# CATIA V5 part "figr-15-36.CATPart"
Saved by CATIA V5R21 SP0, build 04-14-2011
Part number: Part1
Bounding box of the stored display mesh (mm): x -63.331 to 107.433, y -39.139 to 39.139, z 0 to 70.926
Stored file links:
  D:\CATIA V5R21 E-RESOURCES\CATIA-V5R21\catia-v5r21-prt\c15-catia-v5r20-prt\c15-catia-v5r21-figr-15-36.CATPart
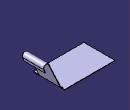
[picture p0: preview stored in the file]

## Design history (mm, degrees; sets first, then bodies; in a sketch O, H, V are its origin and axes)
SheetMetalParameters1: Thickness 1, BendRadius 2, KFactor 0.400515 {= log(min(100,max(20*SheetMetalParameters1.BendRadius,SheetMetalParameters1.Thickness)/SheetMetalParameters1.Thickness))/log(100)/2}, ReliefRadialLength 1, ReliefAxialLength 2, MinimumBendRadius 0
Body1 (main body)
  Sketch1 on xy-plane, origin (0, 0, 0), H (1, 0, 0), V (0, 1, 0)
    line L1 (-63.3311, 39.1393) -> (63.3311, 39.1393)
    line L2 (63.3311, 39.1393) -> (63.3311, -39.1393)
    line L3 (63.3311, -39.1393) -> (-63.3311, -39.1393)
    line L4 (-63.3311, -39.1393) -> (-63.3311, 39.1393)
    horizontal: L1 H, L3 H
    vertical: L2 V, L4 V
    symmetry: L4 L2 V, L1 L3 H
  Wall1: Thickness 1, Profile Sketch1
  d_NewWallOnEdge1: NewWallOnEdge_Edge edge [face of Wall1 | face of Wall1], NewWallOnEdge_Length 67, NewWallOnEdge_HeightLimitOffset 0, NewWallOnEdge_WidthOffset1 -16, NewWallOnEdge_WidthOffset2 -9, NewWallOnEdge_Angle 115, NewWallOnEdge_BendRadiusValue 2 {= SheetMetalParameters1.BendRadius}, NewWallOnEdge_BendTable SheetMetalParameters1, KFacteur 0.400515 {= log(min(100,max(20*d_NewWallOnEdge1.Radius,SheetMetalParameters1.Thickness)/SheetMetalParameters1.Thickness))/log(100)/2}
  Flange1: Angle 4, Length 10, Radius 6, KFacteur 0.5 {= log(min(100,max(20*Flange1.Radius,SheetMetalParameters1.Thickness)/SheetMetalParameters1.Thickness))/log(100)/2}, Guide edge [face of d_NewWallOnEdge1 | face of d_NewWallOnEdge1]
